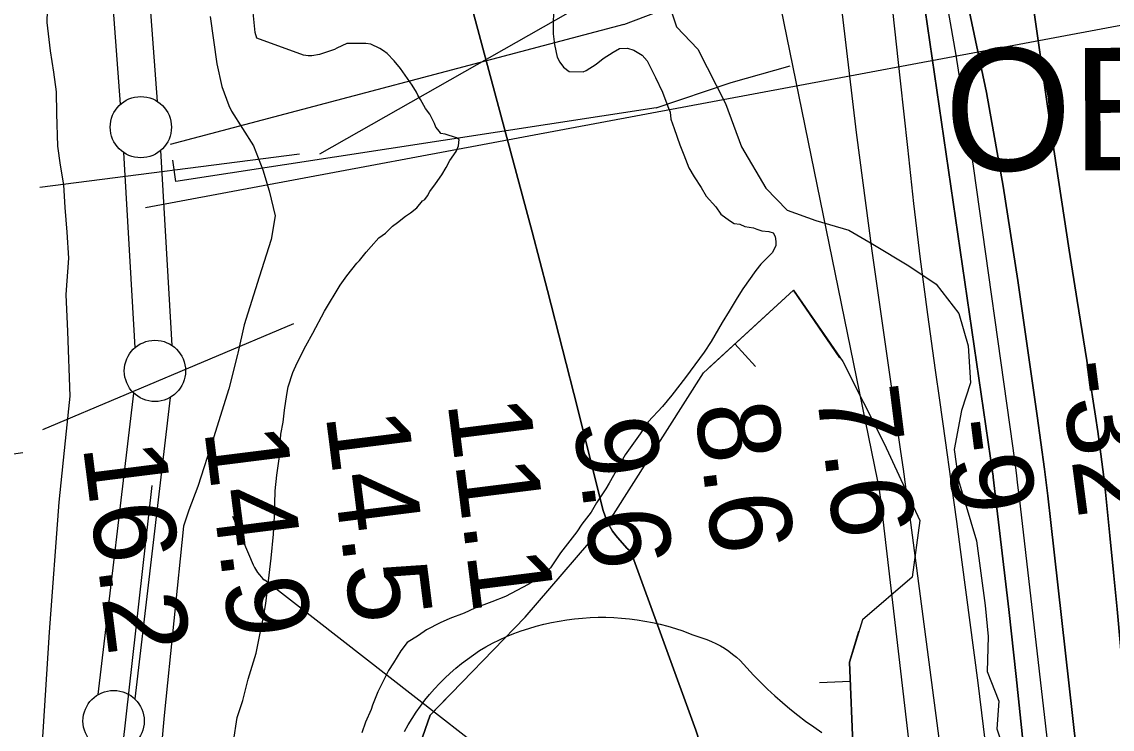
# Model space of a CAD drawing. Extents: x 3651524 to 3689615, y 505651 to 531377.
# Drawn here: x 3657123 to 3658014, y 527633 to 528211 of the extents above; entities that cross this region are included whole.
import ezdxf

# ---------------------------------------------------------------- set-up
doc = ezdxf.new("R2010")
doc.units = 0
for name, color, linetype in [('V-BORW-LINE', 7, 'Continuous'), ('V-CHAN-NAID', 7, 'Continuous'), ('V-FLOD-BASE', 7, 'Continuous'), ('V-LEVE-TOET', 7, 'Continuous'), ('V-RIVR-EDGE', 7, 'Continuous'), ('V-RIVR-RANG', 7, 'Continuous'), ('V-ROAD-CNTR', 7, 'Continuous'), ('V-SITE-VEGE', 7, 'Continuous'), ('V-SURV-LINE', 7, 'Continuous'), ('V-TOPO-DPTH', 7, 'Continuous'), ('V-TOPO-MINR', 7, 'Continuous'), ('V-TOPO-WATR', 7, 'Continuous'), ('V-UTIL-LINE', 7, 'Continuous')]:
    doc.layers.add(name, color=color, linetype=linetype)

msp = doc.modelspace()

# ---------------------------------------------------------------- linework, layer by layer
at = {"layer": 'V-BORW-LINE'}
for p, q in [((3657705.326, 527947.837), (3657722.236, 527929.423)), ((3657799.614, 527672.049), (3657774.635, 527671.021))]:
    msp.add_line(p, q, dxfattribs=at)
for points in [[(3657798.958, 527687.993), (3657801.96, 527615.066), (3657815.726, 527508.88), (3657834.129, 527420.487), (3657827.113, 527342.263), (3657661.946, 527230.338), (3657503.725, 527169.871), (3657425.293, 527162.773), (3657411.305, 527291.911), (3657404.963, 527497.003), (3657456.498, 527644.516), (3657534.001, 527724.558), (3657606.135, 527808.553), (3657679.682, 527924.288), (3657753.197, 527991.795), (3657793.467, 527933.348), (3657827.408, 527866.421), (3657856.53, 527803.466), (3657850.093, 527757.228), (3657809.647, 527722.524), (3657798.958, 527687.993)], [(3657791.235, 527936.588), (3657753.197, 527991.795), (3657684.406, 527928.626)], [(3657798.958, 527687.993), (3657806.724, 527713.08)], [(3657470.714, 527659.198), (3657456.498, 527644.516), (3657404.963, 527497.003), (3657411.305, 527291.911), (3657425.293, 527162.773), (3657503.725, 527169.871), (3657661.946, 527230.338), (3657827.113, 527342.263), (3657834.129, 527420.487), (3657815.726, 527508.88), (3657801.96, 527615.066), (3657798.958, 527687.993)]]:
    msp.add_lwpolyline(points, dxfattribs=at)
at = {"layer": 'V-FLOD-BASE'}
msp.add_lwpolyline([(3657229.121, 527832.182), (3657205.053, 527618.885), (3657197.066, 527503.879), (3657194.729, 527460.001), (3657194.553, 527399.482), (3657196.547, 527322.918), (3657204.946, 527189.902), (3657213.675, 527036.116)], dxfattribs=at)
at = {"layer": 'V-LEVE-TOET'}
for points in [[(3657144.473, 528251.776), (3657143.353, 528210.257), (3657146.025, 528187.082), (3657148.772, 528169.842), (3657150.943, 528153.794), (3657151.309, 528135.988), (3657152.157, 528109.276), (3657154.334, 528093.824), (3657157.097, 528077.768), (3657158.049, 528059.362), (3657159.575, 528039.169), (3657161.082, 528017.79), (3657158.926, 527988.149), (3657160.322, 527957.872), (3657162.024, 527905.043), (3657159.13, 527876.636), (3657153.214, 527818.528), (3657145.339, 527712.419), (3657137.938, 527596.811)], [(3657276.831, 528215.205), (3657282.275, 528176.567), (3657286.193, 528158.125), (3657291.931, 528142.626), (3657294.243, 528137.85), (3657312.28, 528109.733), (3657319.743, 528090.058), (3657324.865, 528072.787), (3657329.946, 528052.549), (3657326.733, 528033.009), (3657316.849, 528002.28), (3657304.487, 527963.276), (3657299.447, 527940.201), (3657299.216, 527939.302), (3657291.96, 527911.222), (3657279.582, 527871.032), (3657266.62, 527831.442), (3657259.251, 527811.958), (3657254.934, 527798.957), (3657239.322, 527644.294), (3657224.824, 527483.684)]]:
    msp.add_lwpolyline(points, dxfattribs=at)
at = {"layer": 'V-RIVR-EDGE'}
msp.add_lwpolyline([(3657650.577, 528227.696), (3657657.729, 528206.667), (3657675.094, 528188.614), (3657697.796, 528144.133), (3657710.916, 528108.682), (3657730.643, 528075.015), (3657748.008, 528056.962), (3657771.4, 528048.5), (3657798.395, 528040.629), (3657818.178, 528029.173), (3657847.55, 528011.691), (3657869.725, 527996.628), (3657888.276, 527972.569), (3657896.015, 527946.136), (3657897.741, 527916.115), (3657890.481, 527893.321), (3657884.399, 527861.519), (3657887.939, 527836.296), (3657902.825, 527787.032), (3657909.898, 527734.186), (3657912.237, 527708.967), (3657911.566, 527680.153), (3657921.112, 527656.116), (3657919.254, 527633.308), (3657926.406, 527612.279)], dxfattribs=at)
at = {"layer": 'V-RIVR-RANG'}
msp.add_line((3657224.054, 528059.186), (3658207.008, 528243.039), dxfattribs=at)
at = {"layer": 'V-ROAD-CNTR'}
for points in [[(3657038.868, 527846.407), (3657047.785, 527848.549), (3657123.721, 527859.106)], [(3657435.651, 527631.365), (3657438.609, 527636.659), (3657441.744, 527641.849), (3657445.056, 527646.928), (3657448.537, 527651.89), (3657452.187, 527656.734), (3657456, 527661.448), (3657459.971, 527666.03), (3657464.094, 527670.474), (3657468.368, 527674.775), (3657472.788, 527678.926), (3657477.345, 527682.926), (3657482.035, 527686.766), (3657486.854, 527690.446), (3657491.795, 527693.958), (3657496.854, 527697.298), (3657502.023, 527700.467), (3657507.299, 527703.457), (3657513.068, 527706.228), (3657518.923, 527708.812), (3657524.86, 527711.208), (3657530.869, 527713.412), (3657536.948, 527715.425), (3657543.085, 527717.242), (3657549.281, 527718.86), (3657555.523, 527720.279), (3657561.808, 527721.498), (3657568.128, 527722.515), (3657574.479, 527723.331), (3657580.855, 527723.943), (3657587.244, 527724.348), (3657593.644, 527724.551), (3657600.049, 527724.547), (3657606.449, 527724.34), (3657612.84, 527723.929), (3657619.216, 527723.312), (3657625.567, 527722.493), (3657631.891, 527721.471), (3657638.176, 527720.244), (3657644.42, 527718.821), (3657650.618, 527717.197), (3657656.76, 527715.376), (3657662.838, 527713.359), (3657668.851, 527711.149), (3657670.977, 527710.291)], [(3657670.977, 527710.291), (3657682.503, 527706.344), (3657686.257, 527704.843), (3657689.927, 527703.147), (3657693.505, 527701.263), (3657696.976, 527699.195), (3657700.337, 527696.946), (3657703.577, 527694.525), (3657706.684, 527691.941), (3657709.649, 527689.197), (3657712.469, 527686.301), (3657715.132, 527683.263), (3657720.661, 527677.339), (3657726.336, 527671.549), (3657732.153, 527665.894), (3657738.104, 527660.381), (3657744.191, 527655.011), (3657750.404, 527649.793), (3657756.741, 527644.724), (3657763.198, 527639.813), (3657769.768, 527635.064), (3657776.451, 527630.474)]]:
    msp.add_lwpolyline(points, dxfattribs=at)
at = {"layer": 'V-SITE-VEGE'}
for points in [[(3657557.12, 528227.089), (3657556.885, 528201.033), (3657557.964, 528192.337), (3657560.188, 528181.892), (3657562.466, 528177.819), (3657565.325, 528173.739), (3657569.927, 528170.223), (3657581.51, 528170.118), (3657583.837, 528171.255), (3657591.988, 528176.393), (3657597.822, 528180.975), (3657605.973, 528186.113), (3657611.208, 528188.96), (3657617.586, 528189.482), (3657622.779, 528187.698), (3657629.693, 528183.582), (3657633.705, 528178.912), (3657640.533, 528165.533), (3657646.215, 528153.32), (3657650.743, 528141.698), (3657652.438, 528137.049), (3657652.965, 528131.253), (3657655.793, 528123.698), (3657660.305, 528110.339), (3657663.704, 528102.2), (3657667.663, 528091.741), (3657672.228, 528084.172), (3657677.94, 528075.435), (3657681.932, 528068.447), (3657689.96, 528059.692), (3657693.964, 528053.863), (3657700.863, 528048.59), (3657704.896, 528046.237), (3657709.522, 528045.616), (3657713.561, 528043.843), (3657720.498, 528042.622), (3657723.383, 528041.436), (3657727.426, 528040.242), (3657733.212, 528039.611), (3657736.675, 528038.421), (3657738.387, 528035.511), (3657738.93, 528031.452), (3657738.897, 528027.979), (3657735.948, 528022.214), (3657726.601, 528013.032), (3657722.498, 528007.857), (3657711.941, 527992.896), (3657707.243, 527985.409), (3657700.773, 527974.467), (3657694.9, 527965.253), (3657686.073, 527949.698), (3657680.203, 527941.064), (3657664.96, 527920.354), (3657653.829, 527905.977), (3657646.217, 527896.78), (3657634.52, 527884.146), (3657628.061, 527874.358), (3657615.746, 527857.098), (3657602.799, 527834.05), (3657599.86, 527829.444), (3657592.229, 527817.932), (3657588.107, 527810.44), (3657580.49, 527800.663), (3657576.378, 527794.331), (3657562.906, 527777.08), (3657554.689, 527764.993), (3657548.263, 527758.681), (3657536.614, 527751.257), (3657517.995, 527741.58), (3657506.951, 527737.048), (3657493.008, 527731.961), (3657484.283, 527727.986), (3657472.665, 527723.46), (3657464.524, 527720.058), (3657453.469, 527714.366), (3657447.059, 527709.791), (3657437.74, 527704.083), (3657432.467, 527697.182), (3657426.587, 527687.39), (3657422.475, 527681.058)], [(3657352.888, 528183.762), (3657314.791, 528197.422), (3657313.675, 528202.069), (3657311.53, 528221.197)], [(3657295.712, 527623.134), (3657298.784, 527642.795), (3657303.541, 527656.652), (3657307.752, 527673.986), (3657314.318, 527695.353), (3657316.74, 527707.491), (3657320.372, 527724.832), (3657322.209, 527735.817), (3657326.595, 527772.841), (3657328.512, 527792.514), (3657329.221, 527806.981), (3657329.987, 527827.826), (3657331.261, 527840.554), (3657333.118, 527853.856), (3657334.458, 527874.112), (3657336.285, 527883.941), (3657337.532, 527893.773), (3657339.383, 527906.498), (3657340.6, 527912.857), (3657344.178, 527924.405), (3657347.725, 527932.48), (3657354.798, 527946.315), (3657360.684, 527956.686), (3657370.109, 527974.553), (3657383.042, 527995.862), (3657388.322, 528003.343), (3657396.522, 528013.694), (3657398.859, 528015.99), (3657404.135, 528022.889), (3657408.229, 528027.485), (3657414.662, 528034.377), (3657419.908, 528038.385), (3657425.751, 528044.121), (3657429.831, 528046.98), (3657436.247, 528052.135), (3657440.327, 528054.994), (3657445.574, 528059), (3657450.26, 528064.749), (3657452.009, 528065.891), (3657454.35, 528068.765), (3657456.117, 528072.224), (3657460.807, 528078.55), (3657466.089, 528086.031), (3657469.613, 528091.79), (3657472.563, 528097.555), (3657477.84, 528105.037), (3657479.62, 528109.653), (3657480.247, 528114.859), (3657477.941, 528116.039), (3657468.7, 528119.016), (3657465.233, 528119.627), (3657464.09, 528121.376), (3657461.227, 528124.876), (3657460.094, 528127.782), (3657456.109, 528135.345), (3657452.676, 528140.008), (3657448.691, 528147.574), (3657446.406, 528151.068), (3657445.269, 528153.394), (3657441.847, 528159.217), (3657432.123, 528172.625), (3657426.97, 528179.039), (3657421.231, 528184.882), (3657418.356, 528187.223), (3657415.477, 528188.988), (3657407.981, 528192.531), (3657403.932, 528193.146), (3657388.298, 528193.287), (3657380.155, 528189.308), (3657378.408, 528188.165), (3657370.859, 528185.916), (3657366.212, 528184.221), (3657359.83, 528183.121), (3657356.935, 528183.145), (3657352.888, 528183.762)], [(3657422.475, 527681.058), (3657413.633, 527663.764), (3657409.482, 527652.799), (3657408.292, 527649.336), (3657403.565, 527638.955), (3657400.592, 527630.294)]]:
    msp.add_lwpolyline(points, dxfattribs=at)
at = {"layer": 'V-SURV-LINE'}
for points in [[(3657215.472, 528387.192), (3657233.587, 528145.879)], [(3657203.67, 528143.642), (3657185.555, 528384.955)], [(3657215.523, 527944.886), (3657206.304, 528104.032)], [(3657236.255, 528105.748), (3657245.474, 527946.601)], [(3657185.343, 527661.445), (3657214.415, 527907.711)], [(3657244.206, 527904.174), (3657215.134, 527657.908)]]:
    msp.add_lwpolyline(points, dxfattribs=at)
for centre in [(3657220.124, 528124.842), (3657231.654, 527925.791), (3657197.895, 527639.828)]:
    msp.add_circle(centre, 25, dxfattribs=at)
at = {"layer": 'V-TOPO-DPTH'}
for points in [[(3657809.068, 526801.277), (3657745.212, 527331.69), (3657733.301, 527408.319), (3657717.947, 527484.126), (3657697.428, 527558.701), (3657673.466, 527632.455), (3657620.745, 527777.551), (3657620.479, 527778.087), (3657618.7, 527779.616), (3657617.744, 527780.374), (3657617.315, 527780.814), (3657609.456, 527789.817), (3657605.543, 527795.006), (3657602.167, 527800.478), (3657599.6, 527806.371), (3657597.572, 527812.547), (3657576.709, 527895.678), (3657564.553, 527943.609), (3657552.238, 527991.498), (3657539.685, 528039.326), (3657526.973, 528087.113), (3657433.517, 528434.932)], [(3657927.623, 528376.161), (3657960.064, 528147.772), (3657966.027, 528106.611), (3657972.143, 528065.473), (3657978.487, 528024.369), (3657984.983, 527983.289), (3657994.222, 527925.9), (3657996.185, 527913.527), (3657998.112, 527901.148), (3657999.982, 527888.761), (3658001.816, 527876.368), (3658003.547, 527863.961), (3658005.176, 527851.542), (3658006.655, 527839.103), (3658008.034, 527826.652), (3658011.724, 527791.356), (3658014.757, 527761.237), (3658017.636, 527731.104), (3658020.285, 527700.95), (3658022.779, 527670.782), (3658091.132, 526803.733)], [(3658091.132, 526803.733), (3658022.779, 527670.782), (3658020.285, 527700.95), (3658017.636, 527731.104), (3658014.757, 527761.237), (3658011.724, 527791.356), (3658008.034, 527826.652), (3658006.655, 527839.103), (3658005.176, 527851.542), (3658003.547, 527863.961), (3658001.816, 527876.368), (3657999.982, 527888.761), (3657998.112, 527901.148), (3657996.185, 527913.527), (3657994.222, 527925.9), (3657984.983, 527983.289), (3657978.487, 528024.369), (3657972.143, 528065.473), (3657966.027, 528106.611), (3657960.064, 528147.772), (3657927.623, 528376.161)], [(3658008.337, 526815.394), (3657950.912, 527511.927), (3657946.111, 527566.73), (3657940.935, 527621.494), (3657935.197, 527676.203), (3657929.085, 527730.874), (3657916.447, 527838.9), (3657916.29, 527840.16), (3657916.116, 527841.417), (3657853.087, 528272.991)], [(3658008.337, 526815.394), (3657950.912, 527511.927), (3657946.111, 527566.73), (3657940.935, 527621.494), (3657935.197, 527676.203), (3657929.085, 527730.874), (3657916.447, 527838.9), (3657916.29, 527840.16), (3657916.116, 527841.417), (3657853.087, 528272.991)], [(3657894.852, 528229.298), (3657910.806, 528153.176), (3657924.473, 528076.609), (3657936.615, 527999.747), (3657952.404, 527889.06), (3657955.407, 527867.307), (3657958.278, 527845.536), (3657960.952, 527823.741), (3657963.495, 527801.929), (3658013.723, 527353.396), (3658024.435, 527253.851), (3658034.572, 527154.251), (3658043.848, 527054.567), (3658052.549, 526954.827)], [(3658052.549, 526954.827), (3658043.848, 527054.567), (3658034.572, 527154.251), (3658024.435, 527253.851), (3658013.723, 527353.396), (3657963.495, 527801.929), (3657960.952, 527823.741), (3657958.278, 527845.536), (3657955.407, 527867.307), (3657952.404, 527889.06), (3657936.615, 527999.747), (3657924.473, 528076.609), (3657910.806, 528153.176), (3657894.852, 528229.298)], [(3657792.895, 528217.269), (3657804.354, 528120.54), (3657817.189, 528023.96), (3657840.756, 527860.04), (3657842.815, 527845.528), (3657844.839, 527831.011), (3657846.809, 527816.487), (3657848.744, 527801.958), (3657911.939, 527320.706), (3657923.817, 527225.306), (3657934.84, 527129.813), (3657944.582, 527034.181), (3657953.47, 526938.456)], [(3657792.895, 528217.269), (3657804.354, 528120.54), (3657817.189, 528023.96), (3657840.756, 527860.04), (3657842.815, 527845.528), (3657844.839, 527831.011), (3657846.809, 527816.487), (3657848.744, 527801.958), (3657911.939, 527320.706), (3657923.817, 527225.306), (3657934.84, 527129.813), (3657944.582, 527034.181), (3657953.47, 526938.456)]]:
    msp.add_lwpolyline(points, dxfattribs=at)
at = {"layer": 'V-TOPO-MINR'}
for points in [[(3657673.438, 528561.566), (3657821.853, 527835.693), (3657822.565, 527831.97), (3657823.212, 527828.237), (3657823.764, 527824.489), (3657824.251, 527820.73), (3657948.003, 526759.686)], [(3657433.517, 528434.932), (3657526.973, 528087.113), (3657539.685, 528039.326), (3657552.238, 527991.498), (3657564.553, 527943.609), (3657576.709, 527895.678), (3657597.572, 527812.547), (3657599.6, 527806.371), (3657602.167, 527800.478), (3657605.543, 527795.006), (3657609.456, 527789.817), (3657617.315, 527780.814), (3657617.744, 527780.374), (3657618.7, 527779.616), (3657620.479, 527778.087), (3657620.745, 527777.551), (3657673.466, 527632.455), (3657697.428, 527558.701), (3657717.947, 527484.126), (3657733.301, 527408.319), (3657745.212, 527331.69), (3657809.068, 526801.277)], [(3657927.623, 528376.161), (3657960.064, 528147.772), (3657966.027, 528106.611), (3657972.143, 528065.473), (3657978.487, 528024.369), (3657984.983, 527983.289), (3657994.222, 527925.9), (3657996.185, 527913.527), (3657998.112, 527901.148), (3657999.982, 527888.761), (3658001.816, 527876.368), (3658003.547, 527863.961), (3658005.176, 527851.542), (3658006.655, 527839.103), (3658008.034, 527826.652), (3658011.724, 527791.356), (3658014.757, 527761.237), (3658017.636, 527731.104), (3658020.285, 527700.95), (3658022.779, 527670.782), (3658091.132, 526803.733)], [(3657853.087, 528272.991), (3657916.116, 527841.417), (3657916.29, 527840.16), (3657916.447, 527838.9), (3657929.085, 527730.874), (3657935.197, 527676.203), (3657940.935, 527621.494), (3657946.111, 527566.73), (3657950.912, 527511.927), (3658008.337, 526815.394)], [(3657870.014, 528274.115), (3657885.967, 528183.736), (3657900.094, 528093.006), (3657932.374, 527862.703), (3657933.748, 527852.637), (3657935.072, 527842.565), (3657936.321, 527832.483), (3657937.522, 527822.395), (3658035.635, 526971.438)], [(3657894.852, 528229.298), (3657910.806, 528153.176), (3657924.473, 528076.609), (3657936.615, 527999.747), (3657952.404, 527889.06), (3657955.407, 527867.307), (3657958.278, 527845.536), (3657960.952, 527823.741), (3657963.495, 527801.929), (3658013.723, 527353.396), (3658024.435, 527253.851), (3658034.572, 527154.251), (3658043.848, 527054.567), (3658052.549, 526954.827)], [(3657834.115, 528220.093), (3657840.477, 528162.624), (3657846.306, 528108.104), (3657851.421, 528062.611), (3657856.866, 528017.158), (3657862.804, 527971.768), (3657869.072, 527926.419), (3657872.598, 527901.896), (3657877.289, 527868.831), (3657881.899, 527835.755), (3657886.386, 527802.661), (3657890.791, 527769.557), (3657903.729, 527670.947), (3657913.989, 527588.468), (3657923.512, 527505.91), (3657931.927, 527423.232), (3657939.605, 527340.473), (3657986.938, 526790.253)], [(3657294.942, 527807.092), (3657311.996, 527767.497), (3657313.049, 527765.315), (3657315.567, 527761.205), (3657317.031, 527759.276), (3657319.855, 527755.872), (3657320.759, 527755.269), (3657321.186, 527755.148), (3657321.405, 527755.107), (3657625.989, 527517.845), (3657633.087, 527513.875), (3657640.184, 527509.902), (3657646.58, 527505.334), (3657652.137, 527500.055), (3657656.436, 527493.708), (3657659.896, 527486.651), (3657693.544, 527393.391), (3657711.211, 527338.655), (3657726.349, 527283.319), (3657737.693, 527227.082), (3657746.507, 527170.245), (3657793.262, 526781.861)]]:
    msp.add_lwpolyline(points, dxfattribs=at)
at = {"layer": 'V-TOPO-WATR'}
msp.add_lwpolyline([(3657792.895, 528217.269), (3657804.354, 528120.54), (3657817.189, 528023.96), (3657840.756, 527860.04), (3657842.815, 527845.528), (3657844.839, 527831.011), (3657846.809, 527816.487), (3657848.744, 527801.958), (3657911.939, 527320.706), (3657923.817, 527225.306), (3657934.84, 527129.813), (3657944.582, 527034.181), (3657953.47, 526938.456)], dxfattribs=at)
at = {"layer": 'V-UTIL-LINE'}
for p, q in [((3657366.306, 528103.103), (3659449.313, 529286.033)), ((3657614.804, 528208.75), (3657244.012, 528110.814)), ((3657349.726, 528102.804), (3657137.571, 528075.623)), ((3657344.78, 527964.349), (3657139.73, 527877.643))]:
    msp.add_line(p, q, dxfattribs=at)
for points in [[(3657614.804, 528208.75), (3657662.881, 528226.862), (3657725.769, 528231.888)], [(3657640.984, 528140.598), (3657702.41, 528161.453), (3657750.427, 528174.99)], [(3657640.984, 528140.598), (3657248.7, 528080.35), (3657246.357, 528097.926)]]:
    msp.add_lwpolyline(points, dxfattribs=at)

# ---------------------------------------------------------------- texts
at = {"layer": 'V-CHAN-NAID'}
msp.add_text(' OBSTRUCTION (103.5)', height=100, rotation=0.184397, dxfattribs=at).set_placement((3657839.561, 528089.083))
at = {"layer": 'V-RIVR-RANG'}
for s, rotation, p in [('-32', 277.439111, (3657970.049, 527932.322)), ('7.6', 277.158326, (3657771.731, 527909.751)), ('11.1', 277.158326, (3657470.545, 527900.435)), ('8.6', 277.158326, (3657672.541, 527897.049)), ('14.5', 277.158326, (3657371.06, 527890.088)), ('9.6', 277.158326, (3657573.351, 527884.347)), ('-9', 277.158326, (3657875.687, 527884.503)), ('14.9', 277.158326, (3657271.837, 527877.648)), ('16.2', 277.158326, (3657172.68, 527864.684))]:
    msp.add_text(s, height=67, rotation=rotation, dxfattribs=at).set_placement(p)

doc.saveas('drawing.dxf')
